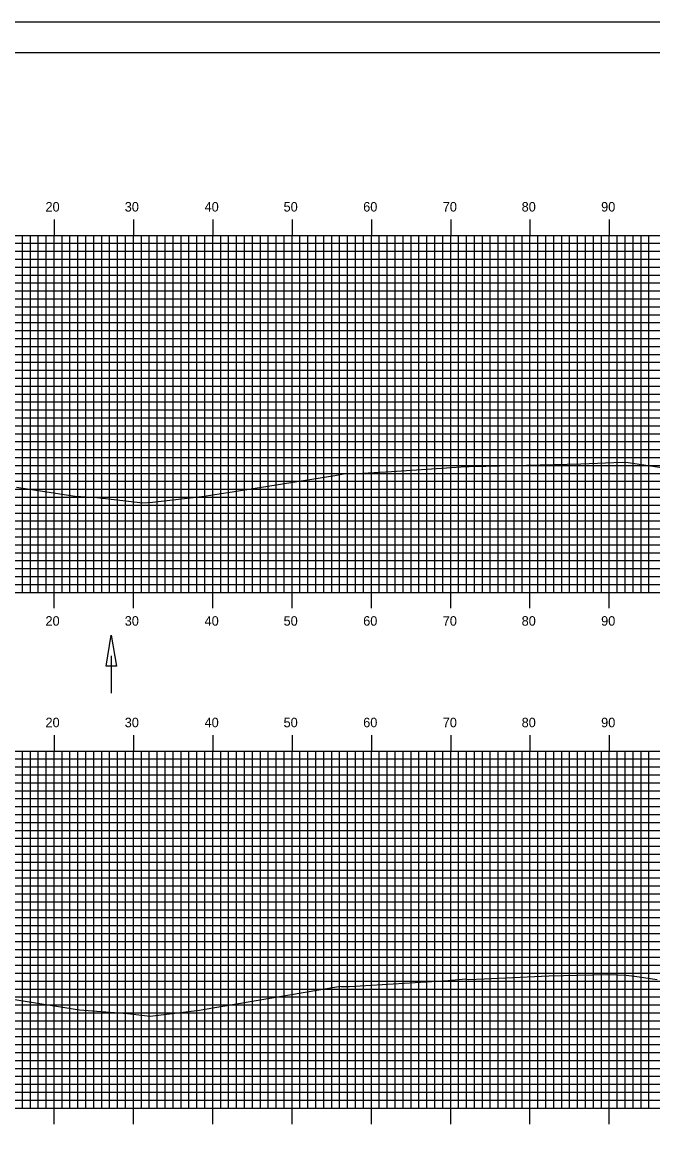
# Model space of a CAD drawing. Extents: x 851139 to 851482, y 366605 to 366825.
# Drawn here: x 851320.9 to 851400.4, y 366685.6 to 366824.9 of the extents above; entities that cross this region are included whole.
import ezdxf

# ---------------------------------------------------------------- set-up
doc = ezdxf.new("R2010")
doc.units = 0
for name, color, linetype in [('BORDER', 7, 'Continuous'), ('D_Drainage_Ditch_Line', 7, 'Continuous'), ('H_V ANNOTATION', 7, 'Continuous'), ('M_Roadway_Centerline', 7, 'Continuous'), ('MAJOR', 7, 'Continuous'), ('MINOR', 7, 'Continuous'), ('PLOT BOUNDARY', 7, 'Continuous'), ('S_Roadway_Centerline', 7, 'Continuous')]:
    doc.layers.add(name, color=color, linetype=linetype)

msp = doc.modelspace()

# ---------------------------------------------------------------- linework, layer by layer
at = {"layer": 'BORDER'}
msp.add_lwpolyline([(851155.34, 366611.06), (851475.34, 366611.06), (851475.34, 366821.06), (851155.34, 366821.06)], close=True, dxfattribs=at)
at = {"layer": 'D_Drainage_Ditch_Line'}
msp.add_line((851332.15, 366745.05), (851332.15, 366740.35), dxfattribs=at)
msp.add_lwpolyline([(851332.81, 366743.74), (851331.5, 366743.74), (851332.15, 366747.68)], close=True, dxfattribs=at)
at = {"layer": 'MAJOR'}
for p, q in [((851324.94, 366800.06), (851324.94, 366798.06)), ((851334.94, 366800.06), (851334.94, 366798.06)), ((851344.94, 366800.06), (851344.94, 366798.06)), ((851354.94, 366800.06), (851354.94, 366798.06)), ((851364.94, 366800.06), (851364.94, 366798.06)), ((851374.94, 366800.06), (851374.94, 366798.06)), ((851384.94, 366800.06), (851384.94, 366798.06)), ((851394.94, 366800.06), (851394.94, 366798.06)), ((851164.94, 366798.06), (851444.94, 366798.06)), ((851164.94, 366798.06), (851444.94, 366798.06)), ((851324.94, 366753.06), (851324.94, 366798.06)), ((851334.94, 366753.06), (851334.94, 366798.06)), ((851344.94, 366753.06), (851344.94, 366798.06)), ((851354.94, 366753.06), (851354.94, 366798.06)), ((851364.94, 366753.06), (851364.94, 366798.06)), ((851374.94, 366753.06), (851374.94, 366798.06)), ((851384.94, 366753.06), (851384.94, 366798.06)), ((851394.94, 366753.06), (851394.94, 366798.06)), ((851164.94, 366793.06), (851444.94, 366793.06)), ((851164.94, 366788.06), (851444.94, 366788.06)), ((851164.94, 366783.06), (851444.94, 366783.06)), ((851164.94, 366778.06), (851444.94, 366778.06)), ((851164.94, 366773.06), (851444.94, 366773.06)), ((851164.94, 366768.06), (851444.94, 366768.06)), ((851164.94, 366763.06), (851444.94, 366763.06)), ((851164.94, 366758.06), (851444.94, 366758.06)), ((851164.94, 366753.06), (851444.94, 366753.06)), ((851164.94, 366753.06), (851444.94, 366753.06)), ((851324.94, 366751.05), (851324.94, 366753.06)), ((851334.94, 366751.05), (851334.94, 366753.06)), ((851344.94, 366751.05), (851344.94, 366753.06)), ((851354.94, 366751.05), (851354.94, 366753.06)), ((851364.94, 366751.05), (851364.94, 366753.06)), ((851374.94, 366751.05), (851374.94, 366753.06)), ((851384.94, 366751.05), (851384.94, 366753.06)), ((851394.94, 366751.05), (851394.94, 366753.06)), ((851324.94, 366735.06), (851324.94, 366733.06)), ((851334.94, 366735.06), (851334.94, 366733.06)), ((851344.94, 366735.06), (851344.94, 366733.06)), ((851354.94, 366735.06), (851354.94, 366733.06)), ((851364.94, 366735.06), (851364.94, 366733.06)), ((851374.94, 366735.06), (851374.94, 366733.06)), ((851384.94, 366735.06), (851384.94, 366733.06)), ((851394.94, 366735.06), (851394.94, 366733.06)), ((851164.94, 366733.06), (851444.94, 366733.06)), ((851164.94, 366733.06), (851444.94, 366733.06)), ((851324.94, 366688.06), (851324.94, 366733.06)), ((851334.94, 366688.06), (851334.94, 366733.06)), ((851344.94, 366688.06), (851344.94, 366733.06)), ((851354.94, 366688.06), (851354.94, 366733.06)), ((851364.94, 366688.06), (851364.94, 366733.06)), ((851374.94, 366688.06), (851374.94, 366733.06)), ((851384.94, 366688.06), (851384.94, 366733.06)), ((851394.94, 366688.06), (851394.94, 366733.06)), ((851164.94, 366728.06), (851444.94, 366728.06)), ((851164.94, 366723.06), (851444.94, 366723.06)), ((851164.94, 366718.06), (851444.94, 366718.06)), ((851164.94, 366713.06), (851444.94, 366713.06)), ((851164.94, 366708.06), (851444.94, 366708.06)), ((851164.94, 366703.06), (851444.94, 366703.06)), ((851164.94, 366698.06), (851444.94, 366698.06)), ((851164.94, 366693.06), (851444.94, 366693.06)), ((851164.94, 366688.06), (851444.94, 366688.06)), ((851164.94, 366688.06), (851444.94, 366688.06)), ((851324.94, 366686.05), (851324.94, 366688.06)), ((851334.94, 366686.05), (851334.94, 366688.06)), ((851344.94, 366686.05), (851344.94, 366688.06)), ((851354.94, 366686.05), (851354.94, 366688.06)), ((851364.94, 366686.05), (851364.94, 366688.06)), ((851374.94, 366686.05), (851374.94, 366688.06)), ((851384.94, 366686.05), (851384.94, 366688.06)), ((851394.94, 366686.05), (851394.94, 366688.06))]:
    msp.add_line(p, q, dxfattribs=at)
at = {"layer": 'MINOR'}
for p, q in [((851164.94, 366797.06), (851444.94, 366797.06)), ((851320.94, 366753.06), (851320.94, 366798.06)), ((851321.94, 366753.06), (851321.94, 366798.06)), ((851322.94, 366753.06), (851322.94, 366798.06)), ((851323.94, 366753.06), (851323.94, 366798.06)), ((851325.94, 366753.06), (851325.94, 366798.06)), ((851326.94, 366753.06), (851326.94, 366798.06)), ((851327.94, 366753.06), (851327.94, 366798.06)), ((851328.94, 366753.06), (851328.94, 366798.06)), ((851329.94, 366753.06), (851329.94, 366798.06)), ((851330.94, 366753.06), (851330.94, 366798.06)), ((851331.94, 366753.06), (851331.94, 366798.06)), ((851332.94, 366753.06), (851332.94, 366798.06)), ((851333.94, 366753.06), (851333.94, 366798.06)), ((851335.94, 366753.06), (851335.94, 366798.06)), ((851336.94, 366753.06), (851336.94, 366798.06)), ((851337.94, 366753.06), (851337.94, 366798.06)), ((851338.94, 366753.06), (851338.94, 366798.06)), ((851339.94, 366753.06), (851339.94, 366798.06)), ((851340.94, 366753.06), (851340.94, 366798.06)), ((851341.94, 366753.06), (851341.94, 366798.06)), ((851342.94, 366753.06), (851342.94, 366798.06)), ((851343.94, 366753.06), (851343.94, 366798.06)), ((851345.94, 366753.06), (851345.94, 366798.06)), ((851346.94, 366753.06), (851346.94, 366798.06)), ((851347.94, 366753.06), (851347.94, 366798.06)), ((851348.94, 366753.06), (851348.94, 366798.06)), ((851349.94, 366753.06), (851349.94, 366798.06)), ((851350.94, 366753.06), (851350.94, 366798.06)), ((851351.94, 366753.06), (851351.94, 366798.06)), ((851352.94, 366753.06), (851352.94, 366798.06)), ((851353.94, 366753.06), (851353.94, 366798.06)), ((851355.94, 366753.06), (851355.94, 366798.06)), ((851356.94, 366753.06), (851356.94, 366798.06)), ((851357.94, 366753.06), (851357.94, 366798.06)), ((851358.94, 366753.06), (851358.94, 366798.06)), ((851359.94, 366753.06), (851359.94, 366798.06)), ((851360.94, 366753.06), (851360.94, 366798.06)), ((851361.94, 366753.06), (851361.94, 366798.06)), ((851362.94, 366753.06), (851362.94, 366798.06)), ((851363.94, 366753.06), (851363.94, 366798.06)), ((851365.94, 366753.06), (851365.94, 366798.06)), ((851366.94, 366753.06), (851366.94, 366798.06)), ((851367.94, 366753.06), (851367.94, 366798.06)), ((851368.94, 366753.06), (851368.94, 366798.06)), ((851369.94, 366753.06), (851369.94, 366798.06)), ((851370.94, 366753.06), (851370.94, 366798.06)), ((851371.94, 366753.06), (851371.94, 366798.06)), ((851372.94, 366753.06), (851372.94, 366798.06)), ((851373.94, 366753.06), (851373.94, 366798.06)), ((851375.94, 366753.06), (851375.94, 366798.06)), ((851376.94, 366753.06), (851376.94, 366798.06)), ((851377.94, 366753.06), (851377.94, 366798.06)), ((851378.94, 366753.06), (851378.94, 366798.06)), ((851379.94, 366753.06), (851379.94, 366798.06)), ((851380.94, 366753.06), (851380.94, 366798.06)), ((851381.94, 366753.06), (851381.94, 366798.06)), ((851382.94, 366753.06), (851382.94, 366798.06)), ((851383.94, 366753.06), (851383.94, 366798.06)), ((851385.94, 366753.06), (851385.94, 366798.06)), ((851386.94, 366753.06), (851386.94, 366798.06)), ((851387.94, 366753.06), (851387.94, 366798.06)), ((851388.94, 366753.06), (851388.94, 366798.06)), ((851389.94, 366753.06), (851389.94, 366798.06)), ((851390.94, 366753.06), (851390.94, 366798.06)), ((851391.94, 366753.06), (851391.94, 366798.06)), ((851392.94, 366753.06), (851392.94, 366798.06)), ((851393.94, 366753.06), (851393.94, 366798.06)), ((851395.94, 366753.06), (851395.94, 366798.06)), ((851396.94, 366753.06), (851396.94, 366798.06)), ((851397.94, 366753.06), (851397.94, 366798.06)), ((851398.94, 366753.06), (851398.94, 366798.06)), ((851399.94, 366753.06), (851399.94, 366798.06)), ((851164.94, 366796.06), (851444.94, 366796.06)), ((851164.94, 366795.06), (851444.94, 366795.06)), ((851164.94, 366794.06), (851444.94, 366794.06)), ((851164.94, 366792.06), (851444.94, 366792.06)), ((851164.94, 366791.06), (851444.94, 366791.06)), ((851164.94, 366790.06), (851444.94, 366790.06)), ((851164.94, 366789.06), (851444.94, 366789.06)), ((851164.94, 366787.06), (851444.94, 366787.06)), ((851164.94, 366786.06), (851444.94, 366786.06)), ((851164.94, 366785.06), (851444.94, 366785.06)), ((851164.94, 366784.06), (851444.94, 366784.06)), ((851164.94, 366782.06), (851444.94, 366782.06)), ((851164.94, 366781.06), (851444.94, 366781.06)), ((851164.94, 366780.06), (851444.94, 366780.06)), ((851164.94, 366779.06), (851444.94, 366779.06)), ((851164.94, 366777.06), (851444.94, 366777.06)), ((851164.94, 366776.06), (851444.94, 366776.06)), ((851164.94, 366775.06), (851444.94, 366775.06)), ((851164.94, 366774.06), (851444.94, 366774.06)), ((851164.94, 366772.06), (851444.94, 366772.06)), ((851164.94, 366771.06), (851444.94, 366771.06)), ((851164.94, 366770.06), (851444.94, 366770.06)), ((851164.94, 366769.06), (851444.94, 366769.06)), ((851164.94, 366767.06), (851444.94, 366767.06)), ((851164.94, 366766.06), (851444.94, 366766.06)), ((851164.94, 366765.06), (851444.94, 366765.06)), ((851164.94, 366764.06), (851444.94, 366764.06)), ((851164.94, 366762.06), (851444.94, 366762.06)), ((851164.94, 366761.06), (851444.94, 366761.06)), ((851164.94, 366760.06), (851444.94, 366760.06)), ((851164.94, 366759.06), (851444.94, 366759.06)), ((851164.94, 366757.06), (851444.94, 366757.06)), ((851164.94, 366756.06), (851444.94, 366756.06)), ((851164.94, 366755.06), (851444.94, 366755.06)), ((851164.94, 366754.06), (851444.94, 366754.06)), ((851320.94, 366688.06), (851320.94, 366733.06)), ((851321.94, 366688.06), (851321.94, 366733.06)), ((851322.94, 366688.06), (851322.94, 366733.06)), ((851323.94, 366688.06), (851323.94, 366733.06)), ((851325.94, 366688.06), (851325.94, 366733.06)), ((851326.94, 366688.06), (851326.94, 366733.06)), ((851327.94, 366688.06), (851327.94, 366733.06)), ((851328.94, 366688.06), (851328.94, 366733.06)), ((851329.94, 366688.06), (851329.94, 366733.06)), ((851330.94, 366688.06), (851330.94, 366733.06)), ((851331.94, 366688.06), (851331.94, 366733.06)), ((851332.94, 366688.06), (851332.94, 366733.06)), ((851333.94, 366688.06), (851333.94, 366733.06)), ((851335.94, 366688.06), (851335.94, 366733.06)), ((851336.94, 366688.06), (851336.94, 366733.06)), ((851337.94, 366688.06), (851337.94, 366733.06)), ((851338.94, 366688.06), (851338.94, 366733.06)), ((851339.94, 366688.06), (851339.94, 366733.06)), ((851340.94, 366688.06), (851340.94, 366733.06)), ((851341.94, 366688.06), (851341.94, 366733.06)), ((851342.94, 366688.06), (851342.94, 366733.06)), ((851343.94, 366688.06), (851343.94, 366733.06)), ((851345.94, 366688.06), (851345.94, 366733.06)), ((851346.94, 366688.06), (851346.94, 366733.06)), ((851347.94, 366688.06), (851347.94, 366733.06)), ((851348.94, 366688.06), (851348.94, 366733.06)), ((851349.94, 366688.06), (851349.94, 366733.06)), ((851350.94, 366688.06), (851350.94, 366733.06)), ((851351.94, 366688.06), (851351.94, 366733.06)), ((851352.94, 366688.06), (851352.94, 366733.06)), ((851353.94, 366688.06), (851353.94, 366733.06)), ((851355.94, 366688.06), (851355.94, 366733.06)), ((851356.94, 366688.06), (851356.94, 366733.06)), ((851357.94, 366688.06), (851357.94, 366733.06)), ((851358.94, 366688.06), (851358.94, 366733.06)), ((851359.94, 366688.06), (851359.94, 366733.06)), ((851360.94, 366688.06), (851360.94, 366733.06)), ((851361.94, 366688.06), (851361.94, 366733.06)), ((851362.94, 366688.06), (851362.94, 366733.06)), ((851363.94, 366688.06), (851363.94, 366733.06)), ((851365.94, 366688.06), (851365.94, 366733.06)), ((851366.94, 366688.06), (851366.94, 366733.06)), ((851367.94, 366688.06), (851367.94, 366733.06)), ((851368.94, 366688.06), (851368.94, 366733.06)), ((851369.94, 366688.06), (851369.94, 366733.06)), ((851370.94, 366688.06), (851370.94, 366733.06)), ((851371.94, 366688.06), (851371.94, 366733.06)), ((851372.94, 366688.06), (851372.94, 366733.06)), ((851373.94, 366688.06), (851373.94, 366733.06)), ((851375.94, 366688.06), (851375.94, 366733.06)), ((851376.94, 366688.06), (851376.94, 366733.06)), ((851377.94, 366688.06), (851377.94, 366733.06)), ((851378.94, 366688.06), (851378.94, 366733.06)), ((851379.94, 366688.06), (851379.94, 366733.06)), ((851380.94, 366688.06), (851380.94, 366733.06)), ((851381.94, 366688.06), (851381.94, 366733.06)), ((851382.94, 366688.06), (851382.94, 366733.06)), ((851383.94, 366688.06), (851383.94, 366733.06)), ((851385.94, 366688.06), (851385.94, 366733.06)), ((851386.94, 366688.06), (851386.94, 366733.06)), ((851387.94, 366688.06), (851387.94, 366733.06)), ((851388.94, 366688.06), (851388.94, 366733.06)), ((851389.94, 366688.06), (851389.94, 366733.06)), ((851390.94, 366688.06), (851390.94, 366733.06)), ((851391.94, 366688.06), (851391.94, 366733.06)), ((851392.94, 366688.06), (851392.94, 366733.06)), ((851393.94, 366688.06), (851393.94, 366733.06)), ((851395.94, 366688.06), (851395.94, 366733.06)), ((851396.94, 366688.06), (851396.94, 366733.06)), ((851397.94, 366688.06), (851397.94, 366733.06)), ((851398.94, 366688.06), (851398.94, 366733.06)), ((851399.94, 366688.06), (851399.94, 366733.06)), ((851164.94, 366732.06), (851444.94, 366732.06)), ((851164.94, 366731.06), (851444.94, 366731.06)), ((851164.94, 366730.06), (851444.94, 366730.06)), ((851164.94, 366729.06), (851444.94, 366729.06)), ((851164.94, 366727.06), (851444.94, 366727.06)), ((851164.94, 366726.06), (851444.94, 366726.06)), ((851164.94, 366725.06), (851444.94, 366725.06)), ((851164.94, 366724.06), (851444.94, 366724.06)), ((851164.94, 366722.06), (851444.94, 366722.06)), ((851164.94, 366721.06), (851444.94, 366721.06)), ((851164.94, 366720.06), (851444.94, 366720.06)), ((851164.94, 366719.06), (851444.94, 366719.06)), ((851164.94, 366717.06), (851444.94, 366717.06)), ((851164.94, 366716.06), (851444.94, 366716.06)), ((851164.94, 366715.06), (851444.94, 366715.06)), ((851164.94, 366714.06), (851444.94, 366714.06)), ((851164.94, 366712.06), (851444.94, 366712.06)), ((851164.94, 366711.06), (851444.94, 366711.06)), ((851164.94, 366710.06), (851444.94, 366710.06)), ((851164.94, 366709.06), (851444.94, 366709.06)), ((851164.94, 366707.06), (851444.94, 366707.06)), ((851164.94, 366706.06), (851444.94, 366706.06)), ((851164.94, 366705.06), (851444.94, 366705.06)), ((851164.94, 366704.06), (851444.94, 366704.06)), ((851164.94, 366702.06), (851444.94, 366702.06)), ((851164.94, 366701.06), (851444.94, 366701.06)), ((851164.94, 366700.06), (851444.94, 366700.06)), ((851164.94, 366699.06), (851444.94, 366699.06)), ((851164.94, 366697.06), (851444.94, 366697.06)), ((851164.94, 366696.06), (851444.94, 366696.06)), ((851164.94, 366695.06), (851444.94, 366695.06)), ((851164.94, 366694.06), (851444.94, 366694.06)), ((851164.94, 366692.06), (851444.94, 366692.06)), ((851164.94, 366691.06), (851444.94, 366691.06)), ((851164.94, 366690.06), (851444.94, 366690.06)), ((851164.94, 366689.06), (851444.94, 366689.06))]:
    msp.add_line(p, q, dxfattribs=at)
at = {"layer": 'PLOT BOUNDARY'}
msp.add_lwpolyline([(851139.15, 366604.94), (851479.15, 366604.94), (851479.15, 366824.94), (851139.15, 366824.94)], close=True, dxfattribs=at)
at = {"layer": 'S_Roadway_Centerline'}
for points in [[(851320.18, 366766.34), (851327.58, 366765.17), (851330.32, 366765.01), (851336.12, 366764.33), (851337.36, 366764.44), (851343.57, 366765.14), (851347.37, 366765.73), (851360.32, 366767.79), (851361.44, 366768), (851363.06, 366768.06), (851367.49, 366768.31), (851374.43, 366768.77), (851376.91, 366768.94), (851377.26, 366768.91), (851379.37, 366768.98), (851391.34, 366769.28), (851396.58, 366769.46), (851397.33, 366769.44), (851398.99, 366769.19), (851408.62, 366767.73)], [(851319.45, 366701.81), (851328.13, 366700.43), (851334.18, 366699.96), (851337.05, 366699.64), (851343.25, 366700.42), (851343.28, 366700.42), (851343.46, 366700.45), (851360.8, 366703.4), (851360.98, 366703.43), (851361.15, 366703.4), (851361.77, 366703.37), (851362.15, 366703.4), (851374.62, 366704.16), (851376.81, 366704.33), (851377.19, 366704.25), (851379.16, 366704.33), (851387.33, 366704.71), (851394.67, 366704.89), (851397.08, 366704.81), (851398.12, 366704.67), (851400.99, 366704.27)]]:
    msp.add_lwpolyline(points, dxfattribs=at)

# ---------------------------------------------------------------- texts
at = {"layer": 'H_V ANNOTATION'}
for s, p in [('20', (851323.85, 366801.06)), ('30', (851333.84, 366801.06)), ('40', (851343.91, 366801.06)), ('50', (851353.87, 366801.06)), ('60', (851363.91, 366801.06)), ('70', (851373.94, 366801.06)), ('80', (851383.89, 366801.06)), ('90', (851393.91, 366801.06)), ('20', (851323.85, 366748.86)), ('30', (851333.84, 366748.86)), ('40', (851343.91, 366748.86)), ('50', (851353.87, 366748.86)), ('60', (851363.91, 366748.86)), ('70', (851373.94, 366748.86)), ('80', (851383.89, 366748.86)), ('90', (851393.91, 366748.86)), ('20', (851323.85, 366736.06)), ('30', (851333.84, 366736.06)), ('40', (851343.91, 366736.06)), ('50', (851353.87, 366736.06)), ('60', (851363.91, 366736.06)), ('70', (851373.94, 366736.06)), ('80', (851383.89, 366736.06)), ('90', (851393.91, 366736.06))]:
    msp.add_text(s, height=1.2, dxfattribs=at).set_placement(p)
at = {"layer": 'M_Roadway_Centerline'}
for s, p in [('C', (851376.91, 366768.94)), ('L', (851376.91, 366768.93)), ('C', (851376.8, 366704.33)), ('L', (851376.81, 366704.32))]:
    msp.add_text(s, height=0.0146, dxfattribs=at).set_placement(p)

doc.saveas('drawing.dxf')
